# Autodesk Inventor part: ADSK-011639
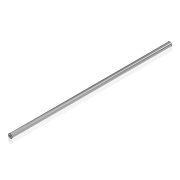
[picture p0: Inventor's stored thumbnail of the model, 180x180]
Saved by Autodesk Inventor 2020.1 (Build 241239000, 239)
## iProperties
Created: 2000-02
Part Number: ADSK-011639
Material: Pearson DGP
Description: SHFTTA,RG,AX,10,375,EE,GUIDE
Document SubType Name: Modeling
Designer: cmcgourin
Density: 7.83 g/cm^3
Appearance: Chrom - poliert
Mass: 3674.26 g
Surface Area: 789.128 cm^2
Volume: 469.254 cm^3
Control State: 0
Master: False
Checked Out: False
Shininess: 60.0
Length Units: 11269
Angle Units: 11279
Time Units: 11290
Mass Units: 11283
Length Display Precision: 3
Angle Display Precision: 2
Compacted: True
Cutlength: 37.56
Material Desc: ROUND,DGP 1144,1.0000 DIA
Material_Number: A084577
Dimensions: 25x25x967 mm
Mass: 3,674 kg
DocNumber: ADSK-011639.ipt
Folder: 01 - Themengebiete\Simplification\01 - Packaging machine\
VDS_Category: 3D Komponenten
Density: 7.83
Volumn: 479.04570446608034
Area: 782.4083803863606
PropertySet Name: Model Information
Author: cmcgourin
Revision Number: -
Title: shaft
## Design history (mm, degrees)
node "Solide1"
  node "Extrusion1" dims "d1" = 967, "d2" = 0
  node "Hole1" dims "d3" = 10.106, "d4" = 9.525, "d5" = 6.35, "d6" = 60 deg, "d7" = 32.3, "d8" = 118 deg, "d18" = 24
  node "Hole2" dims "d9" = 10.106, "d10" = 9.525, "d11" = 6.35, "d12" = 60 deg, "d13" = 32.3, "d14" = 118 deg, "d19" = 24
  node "Chamfer1" dims "d15" = 1, "d16" = 1, "d17" = 45 deg
sketch "Sketch1"
  geometry: C1 r 12.5 at (0, 0); 2 further points
  constraints: 2 coincident, 1 centre point
  dimensions: "d0" = 25 diameter of C1
node "Corps solides"
node "Corps surfaciques"
sketch "Sketch2"
  geometry: C1 r 12.5 at (0, 0) reference; 1 further point
  constraints: 1 coincident
sketch "Sketch3"
  geometry: C1 r 12.5 at (0, 0) reference; 1 further point
  constraints: 1 coincident
